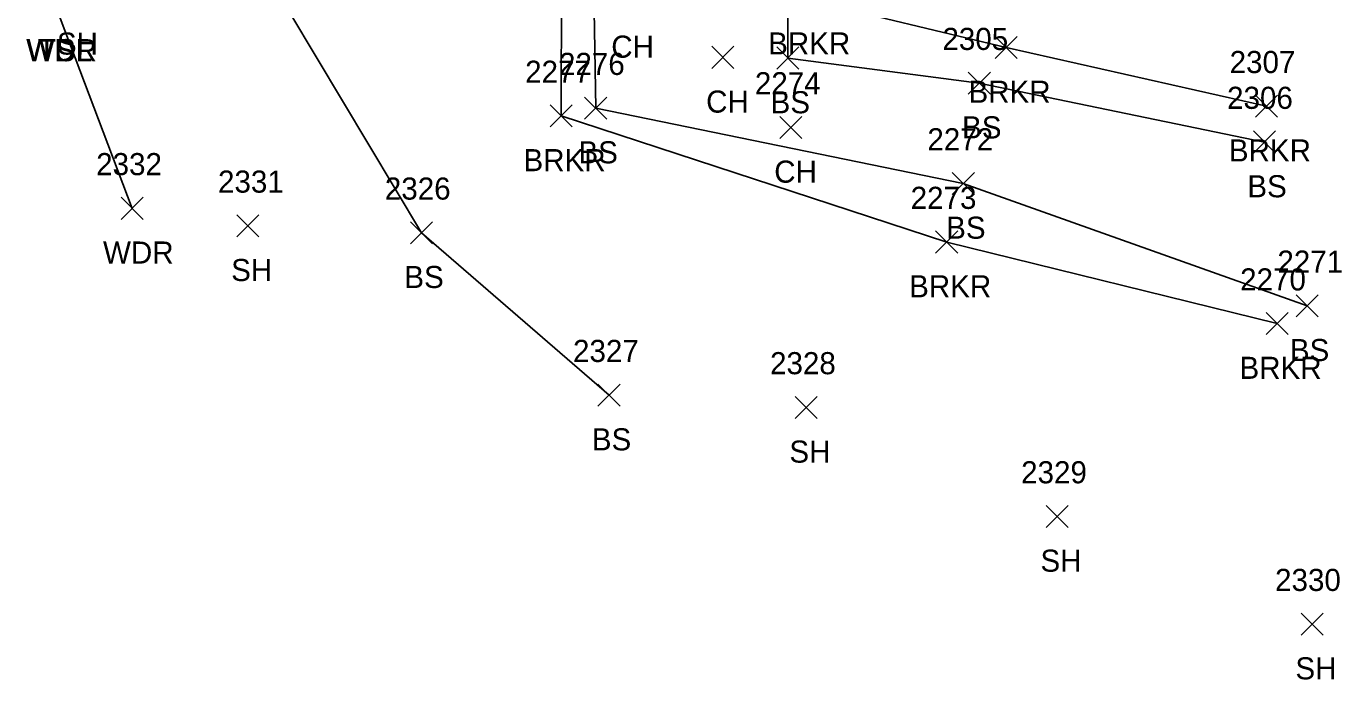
# Model space of a CAD drawing. Extents: x 1699408 to 1700423, y 840176 to 841410.
# Drawn here: x 1699874.9 to 1699993.9, y 840205.7 to 840264.9 of the extents above; entities that cross this region are included whole.
import ezdxf

# ---------------------------------------------------------------- set-up
doc = ezdxf.new("R2010")
doc.units = 0
for name, color, linetype in [('L_A', 7, 'Continuous'), ('L_I', 7, 'Continuous'), ('L_TIC', 7, 'Continuous'), ('LAWA', 7, 'Continuous'), ('LAWE', 7, 'Continuous'), ('LELB', 7, 'Continuous')]:
    doc.layers.add(name, color=color, linetype=linetype)

msp = doc.modelspace()

# ---------------------------------------------------------------- linework, layer by layer
at = {"layer": 'L_TIC'}
for points in [[(1699962.54, 840261.93), (1699964.54, 840263.93)], [(1699964.54, 840261.93), (1699962.54, 840263.93)], [(1699936.91, 840261.04), (1699938.91, 840263.04)], [(1699938.91, 840261.04), (1699936.91, 840263.04)], [(1699942.79, 840260.98), (1699944.79, 840262.98)], [(1699944.79, 840260.98), (1699942.79, 840262.98)], [(1699960.11, 840258.71), (1699962.11, 840260.71)], [(1699962.11, 840258.71), (1699960.11, 840260.71)], [(1699925.41, 840256.45), (1699927.41, 840258.45)], [(1699927.41, 840256.45), (1699925.41, 840258.45)], [(1699986.09, 840256.62), (1699988.09, 840258.62)], [(1699988.09, 840256.62), (1699986.09, 840258.62)], [(1699922.29, 840255.74), (1699924.29, 840257.74)], [(1699924.29, 840255.74), (1699922.29, 840257.74)], [(1699943.07, 840254.7), (1699945.07, 840256.7)], [(1699945.07, 840254.7), (1699943.07, 840256.7)], [(1699985.91, 840253.38), (1699987.91, 840255.38)], [(1699987.91, 840253.38), (1699985.91, 840255.38)], [(1699958.66, 840249.63), (1699960.66, 840251.63)], [(1699960.66, 840249.63), (1699958.66, 840251.63)], [(1699883.49, 840247.38), (1699885.49, 840249.38)], [(1699885.49, 840247.38), (1699883.49, 840249.38)], [(1699893.95, 840245.8), (1699895.95, 840247.8)], [(1699895.95, 840245.8), (1699893.95, 840247.8)], [(1699909.65, 840245.17), (1699911.65, 840247.17)], [(1699911.65, 840245.17), (1699909.65, 840247.17)], [(1699957.16, 840244.33), (1699959.16, 840246.33)], [(1699959.16, 840244.33), (1699957.16, 840246.33)], [(1699989.76, 840238.56), (1699991.76, 840240.56)], [(1699991.76, 840238.56), (1699989.76, 840240.56)], [(1699987.05, 840236.95), (1699989.05, 840238.95)], [(1699989.05, 840236.95), (1699987.05, 840238.95)], [(1699926.62, 840230.48), (1699928.62, 840232.48)], [(1699928.62, 840230.48), (1699926.62, 840232.48)], [(1699944.44, 840229.37), (1699946.44, 840231.37)], [(1699946.44, 840229.37), (1699944.44, 840231.37)], [(1699967.15, 840219.5), (1699969.15, 840221.5)], [(1699969.15, 840219.5), (1699967.15, 840221.5)], [(1699990.21, 840209.76), (1699992.21, 840211.76)], [(1699992.21, 840209.76), (1699990.21, 840211.76)]]:
    msp.add_lwpolyline(points, dxfattribs=at)
at = {"layer": 'LAWA'}
msp.add_lwpolyline([(1699884.49, 840248.38), (1699877.54, 840266.69)], dxfattribs=at)
at = {"layer": 'LAWE'}
for points in [[(1699943.08, 840321.54), (1699948.74, 840315.51), (1699945.93, 840304.68), (1699947.99, 840292.49), (1699945.42, 840267.3), (1699963.54, 840262.93), (1699987.09, 840257.62)], [(1699988.05, 840237.95), (1699958.16, 840245.33), (1699923.29, 840256.74), (1699923.34, 840281.02), (1699928.43, 840290.14), (1699927.27, 840305.65)]]:
    msp.add_lwpolyline(points, dxfattribs=at)
at = {"layer": 'LELB'}
for points in [[(1699990.76, 840239.56), (1699959.66, 840250.63), (1699926.41, 840257.45), (1699926.02, 840280.47), (1699933.8, 840291.66), (1699935.17, 840303.1), (1699929.07, 840313.33), (1699935.34, 840316.5), (1699937.64, 840319.19), (1699942.95, 840320.14), (1699946.53, 840317.37), (1699942.49, 840304.68), (1699943.75, 840292.22), (1699943.79, 840261.98), (1699961.11, 840259.71), (1699986.91, 840254.38)], [(1699877.39, 840286.89), (1699896.35, 840270.09), (1699910.65, 840246.17), (1699927.62, 840231.48)]]:
    msp.add_lwpolyline(points, dxfattribs=at)

# ---------------------------------------------------------------- texts
at = {"layer": 'L_A'}
for s, p in [('SH', (1699877.68, 840262.29)), ('CH', (1699927.82, 840262.01)), ('BRKR', (1699942.01, 840262.3)), ('WDR', (1699874.9, 840261.69)), ('WDL', (1699874.95, 840261.69)), ('TS', (1699875.95, 840261.69)), ('CH', (1699936.4, 840257.04)), ('BS', (1699942.23, 840256.98)), ('BRKR', (1699960.13, 840257.93)), ('BS', (1699959.55, 840254.71)), ('BS', (1699924.85, 840252.45)), ('BRKR', (1699983.68, 840252.62)), ('BRKR', (1699919.88, 840251.74)), ('CH', (1699942.56, 840250.7)), ('BS', (1699985.35, 840249.38)), ('BS', (1699958.11, 840245.63)), ('WDR', (1699881.85, 840243.38)), ('SH', (1699893.44, 840241.8)), ('BS', (1699909.1, 840241.17)), ('BRKR', (1699954.76, 840240.33)), ('BS', (1699989.2, 840234.56)), ('BRKR', (1699984.64, 840232.95)), ('BS', (1699926.06, 840226.48)), ('SH', (1699943.93, 840225.37)), ('SH', (1699966.64, 840215.5)), ('SH', (1699989.7, 840205.76))]:
    msp.add_text(s, height=2, dxfattribs=at).set_placement(p)
at = {"layer": 'L_I'}
for s, p in [('2305', (1699957.77, 840262.71)), ('2307', (1699983.75, 840260.62)), ('2277', (1699920.03, 840259.74)), ('2276', (1699923.09, 840260.45)), ('2274', (1699940.81, 840258.7)), ('2306', (1699983.52, 840257.38)), ('2272', (1699956.41, 840253.63)), ('2332', (1699881.23, 840251.38)), ('2331', (1699892.25, 840249.8)), ('2326', (1699907.34, 840249.17)), ('2273', (1699954.9, 840248.33)), ('2271', (1699988.07, 840242.56)), ('2270', (1699984.7, 840240.95)), ('2327', (1699924.36, 840234.48)), ('2328', (1699942.18, 840233.37)), ('2329', (1699964.89, 840223.5)), ('2330', (1699987.86, 840213.76))]:
    msp.add_text(s, height=2, dxfattribs=at).set_placement(p)

doc.saveas('drawing.dxf')
